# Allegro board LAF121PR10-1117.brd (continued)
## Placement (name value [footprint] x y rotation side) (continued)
J3  -  [JUMP_43X79]  41.12 102.65 270 top
J4  -  [JUMP_43X118]  37.94 55.47 270 top
J5  -  [JUMP_43X79]  39.53 45.69 270 top
JCCG4_T  CVILU_CH31052VA00-NH  [DC021611210]  42.83 115.5 90 bottom
JCRT  ACES_51625-01601-001  [ACES_51625-01601-001_16P-T]  217.65 38.75 90 top
JDIMM1  DEREN_40-42271-26001RHF  [LOTES_ADDR0206-P001A02_260P]  79.15 109.99 90 bottom
JDIMM2  DEREN_40-42261-26001RHF  [LOTES_ADDR0205-P001A02_260P]  66.45 109.99 270 bottom
JEDP1  ACES_51540-04001-P01  [ACES_51540-04001-P01_40P]  212.37 60.45 270 bottom
JFAN1  ACES_50224-00401-001  [ACES_50224-00401-001_4P]  180.51 68.41 45 bottom
JFP  ACES_51522-00601-001  [ACES_51522-00601-001_6P-NPM]  220 30.6 180 bottom
JFP1  ACES_51522-00801-001  [ACES_51522-00801-001_8P]  221 30.6 180 bottom
JH1  ACES_91960-0084N_MX25L3206EM2I  [ACES_91960-0084L_8P-T-NPM]  129.95 40.19 90 bottom
JHDD1  ACES_51625-01201-001  [ACES_51625-01201-001_12P]  190.2 35.7 180 bottom
JHDMI1  CONCR_099AKAC19NBLCNF  [ACON_HMRF6-AK120C_19P-T]  11.05 92.35 90 bottom
JHP1  YUQIU_PJ753-F07J1BE-B  [YUQIU_PJ753-F07J1BE-B_7P-T]  12.65 7.9 90 bottom
JIOB1  ACES_51524-0160N-001  [ACES_51524-0160N-001_16P]  213.2 36.8 180 bottom
JKB1  ACES_50699-03041-P01  [ACES_50699-03041-P01_30P]  82.95 34.05 180 bottom
JKBBL1  ACES_51575-00401-001  [ACES_51575-00401-001_4P-T]  95.05 34.52 180 bottom
JODD1  ACES_50673-0120N-001  [ACES_50673-0120N-001_12P-T]  185.2 64.3 180 bottom
JP2  -  [JUMP_43X39]  158.85 32.2 270 top
JP3  2MM  [JUMP_43X39]  25.89 89.53 180 top
JP4  -  [JUMP_43X79]  190.66 40.42 270 top
JP5  -  [JUMP_43X79]  193.35 65.59 0 top
JP10  -  [JUMP_43X79]  24.04 29.88 270 top
JPWR1  JXT_FP226H-004S1AM  [JXT_FP226H-004S1AM_4P]  221.2 63.65 0 bottom
JRJ45  SANTA_130460-N  [SINGA_2RJ3076-078211F_8P-T]  12.95 77.72 90 bottom
JSPK1  ACES_50224-00401-001  [ACES_50224-00401-001_4P]  16.42 5.88 180 bottom
JSSD1  LCN_DAN05-67306-0103  [LCN_DAN05-67306-0103_75P]  39.38 34.03 180 bottom
JTP1  ACES_51524-0080N-001  [ACES_51524-0080N-001_8P]  125.05 30.5 180 bottom
JUSB1  ACON_TARAN-9R1391  [ACON_TARAN-9R1391_9P]  15.88 56.65 90 bottom
JUSB2  ACON_TARAN-9R1391  [ACON_TARAN-9R1391_9P]  15.88 32.75 90 bottom
JUSBC1  JAE_DX07S024JJ2R1300~D  [JAE_DX07S024JJ2R1300_24P]  7.35 123.82 270 top
JWLAN1  LCN_DAN05-67306-0100  [LCN_DAN05-67306-0100_75P]  79.02 120.65 90 bottom
L1  MCM1012B900F06BP_4P  [INPAQ_MCM1012B900F06BP_4P]  215.73 43.88 180 top
LA1  TAI-TECH HCB1005KF-800T20 0402  [R_0402]  23.92 5.14 180 top
LA2  TAI-TECH HCB1005KF-800T20 0402  [R_0402]  23.92 3.87 180 top
LA3  TAI-TECH HCB1005KF-800T20 0402  [R_0402]  26.83 8.07 270 top
LA4  TAI-TECH HCB1005KF-800T20 0402  [R_0402]  27.88 8.05 270 top
LA6  BLM15PX330SN1D_2P  [MURAT_BLM15PX330SN1D_2P]  18.24 13.58 180 top
LA7  0_0402_5%  [R0402_0OHM]  15.52 20.06 0 bottom
LA8  0_0402_5%  [R0402_0OHM]  18.21 20.06 180 bottom
LA9  BLM15PX330SN1D_2P  [MURAT_BLM15PX330SN1D_2P]  15.61 13.58 0 top
LA10  BLM15BB221SN1D_2P  [MURAT_BLM15BB221SN1D_2P]  35.13 11.49 180 top
LE1  FBMA-L11-160808-800LMT_0603  [KC_FBMA-L11-160808-800LMT_2P]  37.19 87.5 0 top
LE2  FBMA-L11-160808-800LMT_0603  [KC_FBMA-L11-160808-800LMT_2P]  53.67 85.54 270 top
LED1  LTW-295DSKS-5A_YEL-WHITE~D  [LED_LTW-295DSKS-5A_4P]  3.25 133.05 270 bottom
LI1  HCM1012GH900BP_4P  [INPAQ_HCM1012GH900BP_4P]  16.17 94.1 0 top
LI2  HCM1012GH900BP_4P  [INPAQ_HCM1012GH900BP_4P]  16.17 95.94 0 top
LI3  HCM1012GH900BP_4P  [INPAQ_HCM1012GH900BP_4P]  16.17 92.38 0 top
LI4  HCM1012GH900BP_4P  [INPAQ_HCM1012GH900BP_4P]  16.17 90.29 0 top
LT1  MCM1012B900F06BP_4P  [INPAQ_MCM1012B900F06BP_4P]  22.27 131 0 bottom
LT3  MCM1012B900F06BP_4P  [INPAQ_MCM1012B900F06BP_4P]  22.27 129.29 0 bottom
LU1  INPAQ HCM1012GD670A05P  [INPAQ_HCM1012GH900BP_4P]  21.44 58.09 0 top
LU2  INPAQ HCM1012GD670A05P_4P  [INPAQ_HCM1012GH900BP_4P]  21.44 59.81 0 top
LU3  MCM1012B900F06BP_4P  [INPAQ_MCM1012B900F06BP_4P]  31.29 57.78 0 top
LU4  INPAQ HCM1012GD670A05P  [INPAQ_HCM1012GH900BP_4P]  20.29 36.33 90 top
LU5  INPAQ HCM1012GD670A05P  [INPAQ_HCM1012GH900BP_4P]  18.58 36.33 90 top
LU6  MCM1012B900F06BP_4P  [INPAQ_MCM1012B900F06BP_4P]  31.48 39.24 0 bottom
LU7  MCM1012B900F06BP_4P  [INPAQ_MCM1012B900F06BP_4P]  210.53 35.04 270 top
LU8  MCM1012B900F06BP_4P  [INPAQ_MCM1012B900F06BP_4P]  207.87 35.02 270 top
LU13  INPAQ HCM1012GD670A05P  [INPAQ_HCM1012GH900BP_4P]  11.16 123.63 0 top
LU14  INPAQ HCM1012GD670A05P  [INPAQ_HCM1012GH900BP_4P]  12.43 117.91 0 top
LU15  INPAQ HCM1012GD670A05P  [INPAQ_HCM1012GH900BP_4P]  14.31 125.54 180 top
LU16  INPAQ HCM1012GD670A05P  [INPAQ_HCM1012GH900BP_4P]  12.72 119.38 180 top
LV2  BLM15BD121SN1D_0402  [R_0402]  110.11 134.45 270 top
LV3  BLM15BD121SN1D_0402  [R_0402]  109.78 136 59.6 top
LV4  BLM15BD121SN1D_0402  [R_0402]  108.77 134.18 90 bottom
LV6  BLM15BD221SN1D_2P  [MURAT_BLM15BB221SN1D_2P]  126.46 123.65 90 top
LV7  BLM15BD121SN1D_0402  [R_0402]  131.22 119.15 0 top
LV8  BLM15BD121SN1D_0402  [R_0402]  133.82 119.54 180 top
LX1  HCB2012KF-221T30_2P  [TAI-T_HCB2012KF-221T30_2P]  220.97 46.86 0 top
NOREF  -  []  113.08 39.78 0 top
NOREF#2  -  []  6.85 130.5 0 top
NOREF#3  -  []  92.84 -15.43 0 top
NOREF#4  -  []  6.9 112.6 0 top
NOREF#5  -  []  207.45 63.85 0 top
NOREF#6  -  []  126.01 153.05 0 top
NOREF#7  -  []  142.95 117.18 0 top
NOREF#8  -  []  7.4 86.8 0 top
NOREF#9  -  []  8 41.2 0 top
NOREF#10  -  []  137.38 100.81 0 top
NOREF#11  -  []  96.86 53.7 0 top
NOREF#12  -  []  83.03 102.15 0 top
NOREF#13  -  []  77.11 24.94 0 top
NOREF#14  -  []  84.39 53.64 0 top
NOREF#15  -  []  207.45 63.85 0 top
NOREF#16  -  []  -1.24 192.21 0 top
NOREF#17  -  []  169.05 109.5 0 top
NOREF#18  -  []  79.85 93.01 0 top
NOREF#19  -  []  45.5 129.9 0 top
NOREF#20  -  []  93.3 99.96 90 top
NOREF#21  -  []  213.85 65.5 0 top
NOREF#22  -  []  113.08 100.78 0 top
NOREF#23  -  []  137.38 39.78 0 top
NOREF#24  -  []  113.83 93.98 270 top
NOREF#25  -  []  6.67 130.98 0 top
NOREF#26  -  []  99 154 0 top
NOREF#27  -  []  169.05 109.5 0 top
NOREF#28  -  []  101.31 130.35 0 top
NOREF#29  -  []  141.55 27.1 0 top
NOREF#30  -  []  7.9 85.8 0 top
NOREF#31  -  []  134.03 102.94 180 bottom
NOREF#32  -  []  133.97 94.71 180 bottom
NOREF#33  -  []  95.92 50.35 180 bottom
PBATT1  -  [ACES_50458-01001-P01_10P-T]  173.01 40 180 bottom
PC1  1000P_0402_50V7K  [C_0402]  88.18 140.58 270 top
PC2  2200P_0402_25V7K  [C_0402]  87.24 140.58 270 top
PC3  1000P_0402_50V7K  [C_0402]  82.71 148.13 90 top
PC4  2200P_0402_25V7K  [C_0402]  84.62 148.13 90 top
PC5  0.022U_0603_50V7K  [C_0603]  92.01 145.13 270 top
PC6  0.022U_0603_50V7K  [C_0603]  101.47 147.86 180 top
PC7  0.1U_0402_50V7K  [C_0402]  91.99 152.78 0 bottom
PC8  1000P_0603_50V7K  [C_0603]  85.67 147.76 90 top
PC9  2.2U_0402_10V6M  [C_0402]  82.37 141.21 180 top
PC10  0.1U_0402_50V7K  [C_0402]  95.65 144.78 0 bottom
PC11  0.01U_0402_25V7K  [C_0402]  146.62 33.97 270 bottom
PC12  1000P_0402_50V7K  [C_0402]  150.53 39.92 90 bottom
PC13  0.1U_0402_25V6  [C_0402]  169.25 28.94 90 top
PC14  0.1U_0402_25V6  [C_0402]  177.1 28.35 90 top
PC15  10P_0402_50V8J  [C_0402]  89.26 140.63 270 top
PC16  82P_0402_50V8J  [C_0402]  83.66 148.13 90 top
PC17  82P_0402_50V8J  [C_0402]  151.48 39.92 90 bottom
PC18  0.1U_0402_25V7K  [C_0402]  149.58 39.92 90 bottom
PC21  0.1U_0402_10V7K  [C_0402]  92.72 147.52 180 top
PC22  0.1U_0402_10V7K  [C_0402]  86.97 148.26 90 top
PC23  0.1U_0402_10V7K  [C_0402]  88.1 142.65 90 bottom
PC301  1000P_0402_50V7K  [C_0402]  14.09 39.54 180 bottom
PC302  2200P_0402_50V7K  [C_0402]  14.08 42.32 180 bottom
PC303  4.7U_0805_25V6-K  [C_0805]  17.53 41.83 90 top
PC304  4.7U_0805_25V6-K  [C_0805]  16.44 40.97 90 bottom
PC305  0.1U_0402_25V6  [C_0402]  14.12 41.38 180 bottom
PC306  1000P_0402_50V7K  [C_0402]  14.1 40.48 180 bottom
PC307  0.1U_0402_10V7K  [C_0402]  23.48 40.29 90 bottom
PC308  4.7U_0402_6.3V6M  [C_0402]  21.31 43.95 270 top
PC309  680P_0603_50V7K  [C_0603]  22.65 44.38 270 top
PC310  22U_0805_6.3V6M  [C_0805]  24.61 52.77 180 bottom
PC311  22U_0805_6.3V6M  [C_0805]  27.5 52.84 0 bottom
PC312  22U_0805_6.3V6M  [C_0805]  24.53 52.74 180 top
PC313  22U_0805_6.3V6M  [C_0805]  27.5 52.84 0 top
PC314  22U_0805_6.3V6M  [C_0805]  24.63 54.53 180 bottom
PC315  1000P_0402_50V7K  [C_0402]  21.51 46.11 90 bottom
PC316  82P_0402_50V8J  [C_0402]  15.1 40.78 90 bottom
PC501  1000P_0402_50V7K  [C_0402]  25.7 101.85 180 bottom
PC502  2200P_0402_50V7K  [C_0402]  25.7 102.74 180 bottom
PC503  10U_0805_25V6K~D  [C_0805]  28.97 99.08 270 top
PC504  10U_0805_25V6K~D  [C_0805]  28.96 99.08 270 bottom
PC505  0.1U_0402_25V6  [C_0402]  25.7 100.96 180 bottom
PC506  1000P_0402_50V7K  [C_0402]  25.7 100.07 180 bottom
PC507  0.1U_0402_10V7K  [C_0402]  21.87 100.02 270 top
PC508  4.7U_0402_6.3V6M  [C_0402]  23.78 96.69 90 top
PC509  680P_0603_50V7K  [C_0603]  18.77 101.1 90 top
PC510  22U_0805_6.3V6M  [C_0805]  24.1 106.7 270 top
PC511  22U_0805_6.3V6M  [C_0805]  25.82 106.7 270 top
PC512  22U_0805_6.3V6M  [C_0805]  27.53 106.7 270 bottom
PC513  22U_0805_6.3V6M  [C_0805]  25.82 106.7 270 bottom
PC514  22U_0805_6.3V6M  [C_0805]  24.1 106.7 270 bottom
PC515  4.7U_0402_6.3V6M  [C_0402]  24.89 95.55 0 top
PC516  4.7U_0402_6.3V6M  [C_0402]  27.49 92.05 180 bottom
PC517  1000P_0402_50V7K  [C_0402]  25.69 93.04 270 bottom
PC518  82P_0402_50V8J  [C_0402]  25.7 103.63 180 bottom
PC519  22U_0805_6.3V6M  [C_0805]  22.39 106.7 270 top
PC1801  22U_0603_6.3V6M  [C_0603]  180.11 57.52 270 bottom
PC1802  22U_0603_6.3V6M  [C_0603]  174.86 47.03 315 top
PC1803  22U_0603_6.3V6M  [C_0603]  174.86 47.06 315 bottom
PC1804  22U_0603_6.3V6M  [C_0603]  173.41 48.51 135 bottom
PC1805  0.1U_0402_10V7K  [C_0402]  174.62 56.9 90 bottom
PC1806  680P_0402_50V7K  [C_0402]  180.1 53.53 90 top
PC1807  22P_0402_50V8J  [C_0402]  173.77 59.67 0 bottom
PC1808  82P_0402_50V8J  [C_0402]  177.11 60.99 180 bottom
PC1809  0.1U_0402_25V6  [C_0402]  181.22 57.57 270 bottom
PC1810  2200P_0402_50V7K  [C_0402]  177.08 61.88 180 bottom
PC2501  10U_0805_10V6K  [C_0805]  73.63 113.19 90 top
PC2502  10U_0805_10V6K  [C_0805]  64.3 113.5 90 top
PC2503  0.1U_0402_10V7K  [C_0402]  73.19 111.01 270 top
PC2504  1U_0402_10V6K  [C_0402]  72.3 115.43 90 top
PC2505  0.01U_0402_25V7K  [C_0402]  64.74 112.42 270 top
PCA01  2200P_0402_50V7K  [C_0402]  168.37 98.66 90 bottom
PCA02  1000P_0402_50V7K  [C_0402]  167.48 98.66 90 bottom
PCA03  10U_0805_25V6K~D  [C_0805]  164.35 98.14 90 top
PCA04  10U_0805_25V6K~D  [C_0805]  164.34 98.14 90 bottom
PCA05  1000P_0402_50V7K  [C_0402]  166.57 98.65 90 bottom
PCA06  1000P_0402_50V7K  [C_0402]  165.65 98.65 90 bottom
PCA07  0.22U_0402_16V7K  [C_0402]  160.51 86.29 180 bottom
PCA08  680P_0603_50V7K  [C_0603]  155.94 101.72 0 top
PCA101  22U_0603_6.3V6M  [C_0603]  145.88 102.74 180 top
PCA102  22U_0603_6.3V6M  [C_0603]  145.88 101.52 180 top
PCA103  22U_0603_6.3V6M  [C_0603]  145.88 100.3 180 top
PCA104  22U_0603_6.3V6M  [C_0603]  147.04 100.13 270 top
PCA105  22U_0603_6.3V6M  [C_0603]  148.27 100.12 270 top
PCA106  22U_0603_6.3V6M  [C_0603]  150.31 101.23 0 top
PCA107  22U_0603_6.3V6M  [C_0603]  150.31 102.45 0 top
PCA108  22U_0603_6.3V6M  [C_0603]  150.3 103.66 0 top
PCA109  22U_0603_6.3V6M  [C_0603]  150.31 104.88 0 top
PCA110  22U_0603_6.3V6M  [C_0603]  150.31 106.1 0 top
PCA171  470U_X_2VY_R9M  [C_D2]  144.45 103.98 0 bottom
PCA172  470U_X_2VY_R9M  [C_D2]  145.61 99.48 270 bottom
PCB01  0.1U_0402_25V6  [C_0402]  200.25 52.84 270 bottom
PCB02  2200P_0402_50V7K  [C_0402]  199.36 52.84 270 bottom
PCB03  22U_0805_25V6M  [C_0805]  200.6 55.86 0 top
PCB04  22U_0805_25V6M  [C_0805]  200.6 54.14 0 top
PCB05  22U_0805_25V6M  [C_0805]  200.6 55.86 0 bottom
PCB06  22U_0805_25V6M  [C_0805]  200.6 54.14 0 bottom
PCB07  33U_D2_25VM_R40M  [C_EEFCX1E330R-NPM]  192.24 58.17 180 bottom
PCB08  33U_25V_M  [C_6P3X4P5]  192.65 58.26 0 bottom
PCB10  10U_0805_25V6K~D  [C_0805]  181.64 45.97 90 bottom
PCB11  10U_0805_25V6K~D  [C_0805]  181.71 41.49 270 bottom
PCB12  10U_0805_25V6K~D  [C_0805]  181.64 45.97 90 top
PCB13  10U_0805_25V6K~D  [C_0805]  189.54 39.91 270 bottom
PCB14  10U_0805_25V6K~D  [C_0805]  183.42 41.49 270 bottom
PCB15  10U_0805_25V6K~D  [C_0805]  183.42 45.94 90 top
PCB16  10U_0805_25V6K~D  [C_0805]  181.71 41.49 270 top
PCB17  10U_0805_25V6K~D  [C_0805]  183.42 41.49 270 top
PCB18  4.7U_0402_6.3V6M  [C_0402]  201.04 48.07 270 bottom
PCB19  1U_0402_25V6K  [C_0402]  201.13 48.79 180 top
PCB20  1U_0402_25V6K  [C_0402]  201.13 47.85 180 top
PCB21  0.1U_0402_25V6  [C_0402]  180.32 45.21 180 bottom
PCB22  2200P_0402_50V7K  [C_0402]  180.32 46.1 180 bottom
PCB23  2200P_0402_50V7K  [C_0402]  185.52 39.88 225 bottom
PCB24  1000P_0402_50V7K  [C_0402]  180.32 46.99 180 bottom
PCB25  0.22U_0603_25V7K  [C_0603]  199.57 44.9 270 bottom
PCB26  0.1U_0402_25V6  [C_0402]  201.09 50.97 180 bottom
PCB27  1U_0603_50V6K  [C_0603]  203.49 50.71 90 top
PCB28  1U_0402_10V6K  [C_0402]  207.6 51.37 0 bottom
PCB29  1U_0402_10V6K  [C_0402]  203.48 43.73 0 top
PCB30  0.22U_0603_25V7K  [C_0603]  203.07 41.87 270 bottom
PCB31  10U_0805_25V6K~D  [C_0805]  178.09 44.99 90 top
PCB32  10U_0805_25V6K~D  [C_0805]  178.09 44.99 90 bottom
PCB33  4700P_0402_25V7K  [C_0402]  146.64 30.89 90 bottom
PCB34  10P_0402_50V8J  [C_0402]  206.74 45.44 180 top
PCB35  0.1U_0402_25V6  [C_0402]  204.31 41.92 270 top
PCB36  680P_0603_50V7K  [C_0603]  187.28 51.51 270 top
PCB37  680P_0603_50V7K  [C_0603]  188.48 44.42 90 top
PCB38  1U_0402_25V6K  [C_0402]  205.22 41.92 270 top
PCB39  560P_0402_50V7K  [C_0402]  208.23 46.16 0 bottom
PCB40  0.1U_0402_25V6  [C_0402]  210.02 43.48 0 bottom
PCB41  1U_0402_25V6K  [C_0402]  206.13 41.2 180 bottom
PCB42  0.01U_0402_25V7K  [C_0402]  210.04 47.03 270 bottom
PCB43  0.22U_0402_25V6K  [C_0402]  206.14 41.91 270 top
PCB44  0.1U_0402_10V7K  [C_0402]  168.04 34.34 90 top
PCB45  0.1U_0402_25V6  [C_0402]  208.24 42.65 0 top
PCB46  82P_0402_50V8J  [C_0402]  180.32 44.32 180 bottom
PCB47  82P_0402_50V8J  [C_0402]  191.28 61.05 180 bottom
PCF01  22U_0603_6.3V6M  [C_0603]  78.47 113.27 90 top
PCF02  22U_0603_6.3V6M  [C_0603]  87.36 110.07 180 top
PCF03  0.1U_0402_10V7K  [C_0402]  77.84 115.77 90 top
PCF04  1U_0402_10V6K  [C_0402]  81.22 110.61 0 top
PCF05  0.01U_0402_25V7K  [C_0402]  87.23 114.24 90 top
PCF06  22U_0603_6.3V6M  [C_0603]  87.39 111.32 180 top
PCH01  0.1U_0402_25V6  [C_0402]  164.8 50.26 90 top
PCH02  2200P_0402_50V7K  [C_0402]  164.82 50.27 90 bottom
PCH03  10U_0805_25V6K~D  [C_0805]  164.67 49.01 180 bottom
PCH04  10U_0805_25V6K~D  [C_0805]  166.2 49.32 90 bottom
PCH05  22U_0603_6.3V6M  [C_0603]  156.63 43.94 0 top
PCH06  22U_0603_6.3V6M  [C_0603]  156.63 47.62 0 top
PCH07  22U_0603_6.3V6M  [C_0603]  156.63 46.41 0 top
PCH08  22U_0603_6.3V6M  [C_0603]  156.63 45.14 0 top
PCH09  0.1U_0402_25V6  [C_0402]  167.11 47.69 0 top
PCH10  1U_0402_10V6K  [C_0402]  167.17 45.99 0 bottom
PCH11  1U_0402_10V6K  [C_0402]  167.17 44.31 0 top
PCH12  0.1U_0402_10V7K  [C_0402]  162.86 42.57 180 bottom
PCH13  680P_0603_50V7K  [C_0603]  160.38 43.03 0 top
PCH14  330P_0402_50V7K  [C_0402]  169.82 45.96 180 top
PCH15  1000P_0402_50V7K  [C_0402]  163.91 50.27 90 bottom
PCH16  1000P_0402_50V7K  [C_0402]  163.91 50.29 90 top
PCH17  82P_0402_50V8J  [C_0402]  163.05 50.29 180 top
PCH18  100P_0402_50V8J  [C_0402]  165.03 45.28 180 top
PCH19  100P_0402_50V8J  [C_0402]  162.44 44.12 90 top
PCH20  0.1U_0402_25V6  [C_0402]  166.65 50.62 90 top
PCM01  0.1U_0402_25V6  [C_0402]  42.76 28.02 90 top
PCM02  2200P_0402_50V7K  [C_0402]  41.84 28.02 90 top
PCM03  4.7U_0805_25V6-K  [C_0805]  42.48 25.9 270 bottom
PCM04  4.7U_0805_25V6-K  [C_0805]  41.82 25.9 270 top
PCM05  22U_0603_6.3V6M  [C_0603]  49.81 31.84 90 top
PCM06  22U_0603_6.3V6M  [C_0603]  49.79 31.85 90 bottom
PCM07  22U_0603_6.3V6M  [C_0603]  51.01 31.85 90 bottom
PCM08  22U_0603_6.3V6M  [C_0603]  48.6 31.85 90 bottom
PCM09  22U_0603_6.3V6M  [C_0603]  48.6 31.84 90 top
PCM10  22U_0603_6.3V6M  [C_0603]  51.01 31.84 90 top
PCM11  680P_0402_50V7K  [C_0402]  51.98 27.96 180 top
PCM12  0.1U_0402_10V7K  [C_0402]  40.81 27.49 180 top
PCM13  1U_0603_10V6K  [C_0603]  36.76 25.3 270 top
PCM14  1U_0603_10V6K  [C_0603]  32.95 25.3 270 top
PCM15  0.1U_0402_10V7K  [C_0402]  33.63 29.13 180 top
PCM16  0.1U_0402_10V7K  [C_0402]  32.72 30.06 180 top
PCM17  220P_0402_50V8J  [C_0402]  34.04 32.25 0 top
PCM18  0.1U_0402_25V6  [C_0402]  35.86 32.21 90 top
PCM19  0.033U_0402_16V7K  [C_0402]  36.78 32.19 90 top
PCM20  10U_0603_6.3V6M  [C_0603]  38.11 33.75 90 top
PCM21  10U_0603_6.3V6M  [C_0603]  38.32 32.29 0 top
PCM22  1000P_0402_50V7K  [C_0402]  41.84 28.02 90 bottom
PCM23  1000P_0402_50V7K  [C_0402]  42.76 28.02 90 bottom
PCM24  82P_0402_50V8J  [C_0402]  47.47 26.39 270 top
PCS01  0.01U_0402_25V7K  [C_0402]  53.77 117.09 180 top
PCS02  100P_0402_50V8J  [C_0402]  47.47 115.13 270 top
PCS03  220P_0402_50V8J  [C_0402]  50.26 117.33 90 top
PCS04  1200P_0402_50V7K  [C_0402]  48.23 117.9 90 top
PCS05  100P_0402_50V8J  [C_0402]  37.26 127.69 0 bottom
PCS06  1000P_0402_50V7K  [C_0402]  37.27 128.61 0 bottom
PCS07  0.1U_0402_25V6  [C_0402]  40.34 128.7 270 bottom
PCS08  100P_0402_50V8J  [C_0402]  39.44 128.7 270 bottom
PCS09  0.47U_0603_25V7K  [C_0603]  52 136.06 0 top
PCS10  1500P_0402_50V7K  [C_0402]  65.34 138.55 90 top
PCS11  0.1U_0402_10V7K  [C_0402]  58.82 131.76 0 top
PCS12  0.1U_0402_10V7K  [C_0402]  56.42 128.38 90 top
PCS13  0.1U_0402_10V7K  [C_0402]  57.44 124.66 270 top
PCS14  0.1U_0402_10V7K  [C_0402]  56.49 124.66 270 top
PCS15  1000P_0603_50V7K  [C_0603]  77.12 142.64 0 top
PCS16  2.2U_0402_10V6M  [C_0402]  79.73 142.58 0 top
PCS17  0.1U_0402_10V7K  [C_0402]  62.26 126.22 90 top
PCS19  0.1U_0402_25V6  [C_0402]  63.16 124.27 0 top
PCS20  0.1U_0402_25V6  [C_0402]  63.33 117.85 0 top
PCS61  1500P_0402_50V7K  [C_0402]  48.09 134.95 90 top
PCS62  0.1U_0402_10V7K  [C_0402]  40.69 127.77 0 top
PCS63  4.7U_0603_25V6K  [C_0603]  59.46 137.45 225 top
PCV01  10U_0805_25V6K~D  [C_0805]  81.78 134.78 270 bottom
PCV02  10U_0805_25V6K~D  [C_0805]  81.78 134.78 270 top
PCV03  4.7U_0805_25V6-K  [C_0805]  83.56 134.78 270 top
PCV04  2200P_0402_50V7K  [C_0402]  82.23 139.11 180 bottom
PCV05  0.1U_0402_25V6K  [C_0402]  82.23 138.22 180 bottom
PCV06  2200P_0402_50V7K  [C_0402]  80.46 134.95 270 top
PCV07  0.1U_0402_25V6K  [C_0402]  82.23 136.44 180 bottom
PCV08  0.22U_0402_16V7K  [C_0402]  78.39 132.28 270 top
PCV09  680P_0603_50V7K  [C_0603]  92.42 131.71 0 top
PCV10  0.1U_0402_25V6K  [C_0402]  69.63 130.16 90 top
PCV11  1U_0603_10V6K  [C_0603]  80.74 129.73 0 top
PCV12  1U_0603_10V6K  [C_0603]  80.74 131 0 top
PCV13  10U_0805_25V6K~D  [C_0805]  81.69 124.79 90 bottom
PCV14  10U_0805_25V6K~D  [C_0805]  81.69 124.79 90 top
PCV15  4.7U_0805_25V6-K  [C_0805]  83.49 124.81 90 bottom
PCV16  2200P_0402_50V7K  [C_0402]  81.82 122.46 180 top
PCV17  0.1U_0402_25V6  [C_0402]  81.82 123.35 180 top
PCV18  2200P_0402_50V7K  [C_0402]  81.82 122.46 180 bottom
PCV19  0.1U_0402_25V6  [C_0402]  81.82 123.35 180 bottom
PCV20  1000P_0402_50V7K  [C_0402]  68.87 128.53 270 top
PCV21  0.22U_0402_16V7K  [C_0402]  79.68 128.33 180 top
PCV22  0.22U_0402_16V7K  [C_0402]  68.87 126.63 270 top
PCV23  0.22U_0402_16V7K  [C_0402]  70.66 125.79 180 top
PCV24  680P_0603_50V7K  [C_0603]  92.45 128.16 0 top
PCV25  1000P_0402_50V7K  [C_0402]  74.66 125.34 180 top
PCV26  180P_0402_50V8J  [C_0402]  73.68 122.8 0 top
PCV27  330P_0402_50V7K  [C_0402]  75.4 124.39 0 top
PCV28  0.033U_0402_16V7K  [C_0402]  70.96 123.49 90 top
PCV29  390P_0402_50V7K  [C_0402]  75.41 121.08 90 top
PCV30  0.15U_0603_16V7K  [C_0603]  69.21 122.99 180 top
PCV31  330P_0402_50V7K  [C_0402]  72.82 121.03 180 top
PCV32  0.1U_0603_50V7K  [C_0603]  69.21 124.19 180 top
PCV33  820P_0402_50V7K  [C_0402]  71.78 125.34 0 top
PCV34  0.01U_0402_25V7K  [C_0402]  76.44 125.34 180 top
PCV35  4.7U_0805_25V6-K  [C_0805]  83.56 134.78 270 bottom
PCV36  4.7U_0805_25V6-K  [C_0805]  83.48 124.82 90 top
PCV37  0.22U_0402_16V7K  [C_0402]  67.06 129.23 270 top
PCV171  560U_D2_2VM_R4.5M  [C_D2]  102.9 136.8 90 bottom
PCV172  560U_D2_2VM_R4.5M  [C_D2]  103.38 123.89 270 bottom
PCW01  0.1U_0402_25V6  [C_0402]  138.46 108.22 270 bottom
PCW02  2200P_0402_50V7K  [C_0402]  135.66 108.78 270 bottom
PCW03  10U_0805_25V6K~D  [C_0805]  139.78 109.41 270 top
PCW04  10U_0805_25V6K~D  [C_0805]  139.8 109.37 270 bottom
PCW05  22U_0603_6.3V6M  [C_0603]  154.22 111.67 90 top
PCW06  22U_0603_6.3V6M  [C_0603]  154.31 109.23 270 top
PCW07  22U_0603_6.3V6M  [C_0603]  154.23 111.65 90 bottom
PCW08  22U_0603_6.3V6M  [C_0603]  154.31 109.23 270 bottom
PCW09  0.1U_0402_25V6  [C_0402]  138.22 111.51 90 bottom
PCW10  1U_0402_10V6K  [C_0402]  142.54 111.51 180 bottom
PCW11  1U_0402_10V6K  [C_0402]  144.29 111.43 90 bottom
PCW12  0.1U_0402_10V7K  [C_0402]  147.13 108.23 0 top
PCW13  680P_0603_50V7K  [C_0603]  149.8 111.27 90 top
PCW14  330P_0402_50V7K  [C_0402]  147.16 113.52 90 bottom
PCW15  1000P_0402_50V7K  [C_0402]  137.57 108.23 270 bottom
PCW16  1000P_0402_50V7K  [C_0402]  134.71 108.83 270 bottom
PCW17  82P_0402_50V8J  [C_0402]  136.66 108.22 270 bottom
PCZ01  330P_0402_50V7K  [C_0402]  162.94 87.82 180 bottom
PCZ02  390P_0402_50V7K  [C_0402]  160.17 87.99 180 bottom
PCZ03  1000P_0402_50V7K  [C_0402]  161.97 91.21 180 bottom
PCZ04  220P_0402_50V8J  [C_0402]  159.44 88.22 270 top
PCZ05  330P_0402_50V7K  [C_0402]  162.87 89.5 90 bottom
PCZ06  0.022U_0402_25V7K  [C_0402]  160.57 91.37 270 top
PCZ07  0.1U_0603_50V7K  [C_0603]  159.61 91.97 180 top
PCZ08  0.1U_0603_50V7K  [C_0603]  160.71 89.38 0 top
PCZ09  220P_0402_50V8J  [C_0402]  159.77 89.15 180 top
PCZ10  33U_25V_M  [C_25CL33LD]  167.37 75.51 180 bottom
PCZ11  1000P_0402_50V7K  [C_0402]  155.75 89.73 90 bottom
PCZ12  33U_25V_M  [C_25CL33LD]  167.5 82.89 90 bottom
PCZ13  10U_0805_25V6K~D  [C_0805]  164.59 70.58 180 bottom
PCZ14  10U_0805_25V6K~D  [C_0805]  168.03 65.71 270 top
PCZ15  10U_0805_25V6K~D  [C_0805]  168.03 65.71 270 bottom
PCZ16  2200P_0402_50V7K  [C_0402]  167.41 70.16 0 bottom
PCZ17  0.1U_0402_25V6K  [C_0402]  167.41 71.05 0 bottom
PCZ18  0.1U_0402_25V6K  [C_0402]  167.41 69.27 0 bottom
PCZ19  10U_0805_25V6K~D  [C_0805]  164.59 70.59 180 top
PCZ20  2200P_0402_50V7K  [C_0402]  167.41 68.38 0 bottom
PCZ21  0.1U_0402_25V6K  [C_0402]  154.85 91.08 270 bottom
PCZ22  1U_0603_10V6K  [C_0603]  153.06 80.62 0 top
PCZ23  1U_0603_10V6K  [C_0603]  155.75 80.56 315 top
PCZ24  0.22U_0402_16V7K  [C_0402]  156.24 81.72 90 top
PCZ25  1000P_0402_50V7K  [C_0402]  152.93 89.96 90 bottom
PCZ26  680P_0603_50V7K  [C_0603]  161.02 60.6 90 top
PCZ27  0.22U_0402_16V7K  [C_0402]  150.3 89.57 180 top
PCZ28  0.22U_0402_16V7K  [C_0402]  150.3 88.68 180 top
PCZ29  1000P_0402_50V7K  [C_0402]  147 84.89 90 top
PCZ30  150P_0402_50V8J  [C_0402]  150.35 85.81 270 top
PCZ31  330P_0402_50V7K  [C_0402]  147.86 84.06 270 top
PCZ32  0.033U_0402_16V7K  [C_0402]  148.17 87.77 0 top
PCZ33  390P_0402_50V7K  [C_0402]  148.78 84.06 270 top
PCZ34  0.15U_0603_16V7K  [C_0603]  148.32 88.69 90 top
PCZ35  2200P_0402_50V7K  [C_0402]  155.7 74.33 0 top
PCZ36  33U_D2_25VM_R40M  [C_EEFCX1E330R-NPM]  167.79 75.51 0 bottom
PCZ37  33U_D2_25VM_R40M  [C_EEFCX1E330R-NPM]  167.53 82.69 270 bottom
PCZ38  10U_0805_25V6K~D  [C_0805]  159.04 77.44 270 bottom
PCZ39  2200P_0402_50V7K  [C_0402]  155.61 74.56 0 bottom
PCZ40  0.1U_0402_25V6K  [C_0402]  155.61 73.63 0 bottom
PCZ41  10U_0805_25V6K~D  [C_0805]  157.32 77.44 270 bottom
PCZ42  330P_0402_50V7K  [C_0402]  151 85.72 0 bottom
PCZ43  10U_0805_25V6K~D  [C_0805]  157.32 77.44 270 top
PCZ44  10U_0805_25V6K~D  [C_0805]  159.04 77.44 270 top
PCZ45  0.1U_0402_25V6K  [C_0402]  155.7 73.44 0 top
PCZ46  0.1U_0603_50V7K  [C_0603]  149.26 88.9 90 bottom
PCZ47  820P_0402_50V7K  [C_0402]  146.82 90.62 0 bottom
PCZ48  0.22U_0402_16V7K  [C_0402]  152.74 81.64 90 top
PCZ49  0.01U_0402_25V7K  [C_0402]  151.47 87.82 0 bottom
PCZ50  680P_0603_50V7K  [C_0603]  159.44 60.6 90 top
PCZ101  22U_0603_6.3V6M  [C_0603]  170.4 54.9 0 top
PCZ102  22U_0603_6.3V6M  [C_0603]  170.39 56.14 0 top
PCZ103  22U_0603_6.3V6M  [C_0603]  126.32 67.2 90 top
PCZ104  22U_0603_6.3V6M  [C_0603]  127.54 67.2 90 top
PCZ105  22U_0603_6.3V6M  [C_0603]  128.76 67.2 90 top
PCZ106  22U_0603_6.3V6M  [C_0603]  123.07 65.4 270 top
PCZ107  22U_0603_6.3V6M  [C_0603]  124.29 65.4 270 top
PCZ108  22U_0603_6.3V6M  [C_0603]  125.51 65.4 270 top
PCZ109  22U_0603_6.3V6M  [C_0603]  126.73 65.4 270 top
PCZ110  22U_0603_6.3V6M  [C_0603]  127.95 65.4 270 top
PCZ111  22U_0603_6.3V6M  [C_0603]  131.25 73.48 270 top
PCZ112  22U_0603_6.3V6M  [C_0603]  130.02 74.1 270 top
PCZ113  22U_0603_6.3V6M  [C_0603]  132.56 72.96 270 top
PCZ114  22U_0603_6.3V6M  [C_0603]  130.13 69.13 90 top
PCZ115  22U_0603_6.3V6M  [C_0603]  154.38 54.17 270 top
PCZ116  22U_0603_6.3V6M  [C_0603]  162.25 54.17 270 top
PCZ117  22U_0603_6.3V6M  [C_0603]  163.52 54.17 270 top
PCZ118  22U_0603_6.3V6M  [C_0603]  167.27 54.17 270 top
PCZ119  22U_0603_6.3V6M  [C_0603]  166 54.17 270 top
PCZ120  22U_0603_6.3V6M  [C_0603]  164.73 54.17 270 top
PCZ171  470U_X_2VY_R9M  [C_D2]  154.42 51.7 0 bottom
PCZ172  470U_X_2VY_R9M  [C_D2]  149.94 59.28 270 bottom
PCZ173  470U_X_2VY_R9M  [C_D2]  170.84 53.65 90 bottom
PCZ174  470U_X_2VY_R9M  [C_D2]  148.05 63.48 90 bottom
PD1  -  [TVNST52302AB0_SOT523-3]  54.07 118.3 90 top
PD2  -  [BAV99W_SC70-3]  61.5 120.81 0 top
PD3  -  [BAV99W_SC70-3]  61.5 116.1 180 top
PD4  S SCH DIO 5A 100V 15UA 0.88V TO227-3  [PDS5100H-13_POWERDI5-3]  96.51 140.89 180 top
PD5  -  [TVNST52302AB0_SOT523-3]  166.82 40.38 180 top
PD6  -  [TVNST52302AB0_SOT523-3]  170.02 39.38 180 top
PD10  -  [LRB715FT1G_SOT323-3]  94 150.96 90 top
PD11  -  [LRB715FT1G_SOT323-3]  82.63 138.14 0 top
PD12  -  [DFLS160-7_POWERDI123-2]  84.68 146.19 0 top
PD501  -  [SDMK0340L-7-F_SOD323-2]  28.86 88.01 90 bottom
PDB01  -  [SDMK0340L-7-F_SOD323-2]  204.19 54.61 0 bottom
PDB02  -  [SDMK0340L-7-F_SOD323-2]  204.19 56.32 0 bottom
PDB03  -  [SDMK0340L-7-F_SOD323-2]  203.35 58.88 135 bottom
PDB04  -  [BAT54CW_SOT323-3]  167.6 37.12 270 top
PDB05  -  [SDMK0340L-7-F_SOD323-2]  169.4 36.66 270 top
PDS01  -  [BAT54CW_SOT323-3]  54.71 120.01 180 top
PDS02  S SCH DIO 5A 100V 15UA 0.88V TO227-3  [PDS5100H-13_POWERDI5-3]  65.1 134.23 180 top
PDS03  -  [LRB715FT1G_SOT323-3]  53.43 119.3 90 top
PDS04  -  [SDMK0340L-7-F_SOD323-2]  45.25 121.59 270 top
PDS05  -  [SDMK0340L-7-F_SOD323-2]  47.54 121.79 0 top
PDS06  -  [SDMK0340L-7-F_SOD323-2]  47.54 120.07 0 top
PH1  100K_0402_1%_TSM0B104F4251RZ  [R_0402]  120.75 47.67 90 top
PHA01  10K_0402_5%_ERTJ0ER103J  [R_0402]  156.4 93.45 180 bottom
PHA02  470K_0402_5%_TSM0B474J4702RE  [R_0402]  159.94 94.55 180 bottom
PHV01  470K_0402_5%_TSM0B474J4702RE  [R_0402]  90.25 121.6 0 bottom
PHV02  10K_0402_5%_ERTJ0ER103J  [R_0402]  94.2 119.85 135 bottom
PHZ01  470K_0402_5%_TSM0B474J4702RE  [R_0402]  160.14 71.36 90 bottom
PHZ02  10K_0402_5%_ERTJ0ER103J  [R_0402]  152.31 62.77 270 bottom
PJP1  JUMP_43X79  [JUMP_43X79-NPM]  88.44 144.05 90 top
PJP2  JUMP_43X79  [JUMP_43X79-NPM]  74.29 145.17 90 top
PJP3  JUMP_43X79  [JUMP_43X79-NPM]  148.98 35.84 90 bottom
PJP301  JUMP_43X39  [JUMP_43X39-NPM]  18.7 37.62 90 bottom
PJP302  -  [JUMP_43X118]  28.49 56.35 0 bottom
PJP501  JUMP_43X79  [JUMP_43X79-NPM]  28.04 102.84 270 bottom
PJP502  -  [JUMP_43X79]  24.42 108.54 90 bottom
PJP503  -  [JUMP_43X79]  28.28 108.57 90 bottom
PJP1801  -  [JUMP_43X39]  180.78 59.61 180 top
PJP1802  -  [JUMP_43X79]  173.03 46.41 225 bottom
PJP2501  -  [JUMP_43X39]  75.89 114.75 270 top
PJP2502  -  [JUMP_43X39]  60.59 112.2 180 top
PJPA01  -  [JUMP_43X79]  166.06 95.62 180 bottom
PJPB01  PAD-OPEN 4X4M  [JUMP_43X118-NPM]  187.32 58.51 0 bottom
PJPDC1  ACES_50458-00601-001  [ACES_50458-00601-001_6P-T]  75.27 143.96 0 bottom
PJPF01  -  [JUMP_43X39]  79.54 110.29 90 top
PJPF02  -  [JUMP_43X39]  89.74 112.74 0 top
PJPH01  JUMP_43X39  [JUMP_43X39-NPM]  168.18 50.55 270 bottom
PJPH02  -  [JUMP_43X118]  155.84 35.94 180 top
PJPM01  JUMP_43X39  [JUMP_43X39-NPM]  49.02 25.12 90 top
PJPM02  -  [JUMP_43X118]  44.8 31.69 90 bottom
PJPM03  -  [JUMP_43X39]  40.12 33.92 90 top
PJPS01  PAD-OPEN 4X4M  [JUMP_43X118]  45.24 137.88 180 bottom
PJPV01  JUMP_43X79  [JUMP_43X79-NPM]  88.65 140.25 180 bottom
PJPW01  JUMP_43X39  [JUMP_43X39-NPM]  135.2 111.2 270 bottom
PJPW02  -  [JUMP_43X118]  157.52 111.65 90 bottom
PJPZ01  JUMP_43X79  [JUMP_43X79-NPM]  171.67 78.91 135 bottom
PL1  5A Z150 20M 1210_2P  [5A_Z150_1210_2P]  88.44 143.25 90 top
PL2  5A Z150 20M 1210_2P  [5A_Z150_1210_2P]  74.29 144.37 90 top
PL3  BLM15AG102SN1D_2P  [MURAT_BLM15AG102SN1D_2P]  56.49 116.79 90 top
PL4  5A Z150 20M 1210_2P  [5A_Z150_1210_2P]  148.98 35.04 90 bottom
PL301  1.5UH_9A_20%_7X7X3_M  [L_7X7X3_M_2P]  26.1 43.87 90 bottom
PL311  5A_Z120_25M_0805_2P  [TAI-T_HCB2012KF-121T50_2P]  18.7 37.22 90 bottom
PL501  1.5UH_9A_20%_7X7X3_M  [L_7X7X3_M_2P]  19.34 98.82 90 bottom
PL511  5A Z150 20M 1210_2P  [5A_Z150_1210_2P]  28.1 103.66 270 bottom
PL1801  1UH_6.6A_20%_5X5X3_M  [L_5X5X3_M_2P]  177.35 53.83 270 bottom
PL1811  5A_Z120_25M_0805_2P  [TAI-T_HCB2012KF-121T50_2P]  182.2 58.9 180 bottom
PLA01  0.15UH_MMD-06DZER15MEM1L__36A_20%  [L_7X7X4_M]  156 97.73 180 bottom
PLB01  1UH_PCMB104T-1R0MH_18A_20%  [CYNTE_PCMB104T-1R0MH_2P]  187.88 52.98 270 bottom
PLB11  5A Z150 20M 1210_2P  [5A_Z150_1210_2P]  186.52 58.51 0 bottom
PLH01  1UH_11A_20%_7X7X3_M  [L_7X7X3_M_2P]  160.35 45.59 180 bottom
PLH11  5A_Z120_25M_0805_2P  [TAI-T_HCB2012KF-121T50_2P]  168.18 50.95 270 bottom
PLM01  1UH_11A_20%_7X7X3_M  [L_7X7X3_M_2P]  54.73 27.6 180 bottom
PLM11  5A_Z120_25M_0805_2P  [TAI-T_HCB2012KF-121T50_2P]  49.02 24.72 90 top
PLS11  5A_Z120_25M_0805_2P  [TAI-T_HCB2012KF-121T50_2P]  37 130.02 0 bottom
PLS12  5A_Z120_25M_0805_2P  [TAI-T_HCB2012KF-121T50_2P]  37 131.81 0 bottom
PLV01  0.22UH_24A_20%_7X7X4_MOLDING  [L_7X7X4_M]  97.21 122.95 135 bottom
PLV02  0.22UH_24A_20%_7X7X4_MOLDING  [L_7X7X4_M]  97.39 137.94 225 bottom
PLV11  5A Z150 20M 1210_2P  [5A_Z150_1210_2P]  89.44 140.21 180 bottom
PLW01  1UH_6.6A_20%_5X5X3_M  [L_5X5X3_M_2P]  147.39 110.16 0 bottom
PLW11  5A_Z120_25M_0805_2P  [TAI-T_HCB2012KF-121T50_2P]  135.2 111.6 270 bottom
PLZ01  5A Z150 20M 1210_2P  [5A_Z150_1210_2P]  170.31 80.19 315 bottom
PLZ02  0.15UH_MMD-06DZER15MEM1L__36A_20%  [L_7X7X4_M]  164.43 62.12 270 bottom
PLZ03  0.15UH_MMD-06DZER15MEM1L__36A_20%  [L_7X7X4_M]  156.51 64.41 270 bottom
PQ1  -  [FDV301N-G_SOT23-3]  57.95 118.35 0 top
PQ2  -  [MMST3904-7-F_SOT323-3]  59.53 115.88 90 top
PQ3  -  [AON7409_DFN8-5]  93.55 146.07 270 top
PQ4  -  [AON7409_DFN8-5]  101.13 144.37 90 top
PQ5  2N7002KW_SOT323-3  [DMN65D8LW-7_SOT323-3]  91.71 149.69 0 bottom
PQ6  2N7002KW_SOT323-3  [DMN65D8LW-7_SOT323-3]  93.86 146.16 180 bottom
PQ11  2N7002KW_SOT323-3  [DMN65D8LW-7_SOT323-3]  174.09 30.35 90 top
PQ12  2N7002KDW_SOT363-6  [DMN65D8LDW-7_SOT363-6]  172.13 29.25 90 top
PQ13  2N7002KDW_SOT363-6  [DMN65D8LDW-7_SOT363-6]  173.28 33.99 0 top
PQ15  2N7002KW_SOT323-3  [DMN65D8LW-7_SOT323-3]  93.78 148.52 270 bottom
PQ16  2N7002KW_SOT323-3  [DMN65D8LW-7_SOT323-3]  90.75 148.48 270 top
PQ17  2N7002KW_SOT323-3  [DMN65D8LW-7_SOT323-3]  89.82 147.37 180 bottom
PQ18  2N7002KW_SOT323-3  [DMN65D8LW-7_SOT323-3]  91.1 143.51 90 bottom
PQ19  -  [AO3409_SOT23-3]  101.28 146.77 270 bottom
PQ20  2N7002KW_SOT323-3  [DMN65D8LW-7_SOT323-3]  94.72 142.54 135 bottom
PQA01  AON6992_DFN5X6D-8-7  [AON6970_DFN5X6D-8-7]  162.61 96.11 180 bottom
PQB01  -  [AON6994_DFN5X6D-8-7]  194.27 53.58 0 bottom
PQB02  -  [AON6994_DFN5X6D-8-7]  194.5 37.7 135 bottom
PQB03  -  [AON7409_DFN8-5]  149.98 30.46 180 bottom
PQB04  2N7002KW_SOT323-3  [DMN65D8LW-7_SOT323-3]  163.6 32.49 0 top
PQH01  2N7002KW_SOT323-3  [DMN65D8LW-7_SOT323-3]  165.45 43.53 270 top
PQH02  2N7002KDW_SOT363-6  [DMN65D8LDW-7_SOT363-6]  167.63 50.24 270 top
PQM01  PE642DT_PDFN8-10  [AON7934_DFN3X3A8-10]  44.08 28.09 0 bottom
PQS01  -  [AON7409_DFN8-5]  54.11 139.56 270 top
PQS02  -  [AON7409_DFN8-5]  63.95 137.63 90 top
PQS03  2N7002KDW_SOT363-6  [DMN65D8LDW-7_SOT363-6]  56.47 130.87 0 top
PQS04  2N7002KW_SOT323-3  [DMN65D8LW-7_SOT323-3]  54.52 131.12 0 top
PQS05  2N7002KDW_SOT363-6  [DMN65D8LDW-7_SOT363-6]  58.2 129.68 270 top
PQS06  -  [AO3409_SOT23-3]  62.18 129.54 270 top
PQS07  2N7002KW_SOT323-3  [DMN65D8LW-7_SOT323-3]  65.31 126.11 270 top
PQS08  2N7002KW_SOT323-3  [DMN65D8LW-7_SOT323-3]  49.5 125.21 0 top
PQS10  2N7002KDW_SOT363-6  [DMN65D8LDW-7_SOT363-6]  63.37 121.4 0 top
PQS11  2N7002KW_SOT323-3  [DMN65D8LW-7_SOT323-3]  65.31 119.57 270 top
PQS12  2N7002KW_SOT323-3  [DMN65D8LW-7_SOT323-3]  50.65 129.22 90 top
PQS13  -  [AO3409_SOT23-3]  50.17 133.47 270 top
PQS14  2N7002KW_SOT323-3  [DMN65D8LW-7_SOT323-3]  69 135.44 0 top
PQS30  2N7002KDW_SOT363-6  [DMN65D8LDW-7_SOT363-6]  45.01 123.46 90 top
PQS61  -  [AON7409_DFN8-5]  50.68 137.63 90 top
PQS62  2N7002KW_SOT323-3  [DMN65D8LW-7_SOT323-3]  57.23 135.84 0 top
PQS63  -  [AO3409_SOT23-3]  44.84 137.59 180 top
PQS64  2N7002KW_SOT323-3  [DMN65D8LW-7_SOT323-3]  40.65 130.83 0 top
PQV01  -  [AON6994_DFN5X6D-8-7]  85.17 122.38 0 top
PQV02  -  [AON6994_DFN5X6D-8-7]  88.98 122.38 180 bottom
PQV03  -  [AON6994_DFN5X6D-8-7]  89.03 137.5 180 top
PQV04  -  [AON6994_DFN5X6D-8-7]  85.22 137.5 0 bottom
PQZ01  AON6994_DFN5X6D-8-7  [AON6970_DFN5X6D-8-7]  166.49 68.89 270 bottom
PQZ02  AON6994_DFN5X6D-8-7  [AON6970_DFN5X6D-8-7]  166.48 65.1 90 top
PQZ03  AON6994_DFN5X6D-8-7  [AON6970_DFN5X6D-8-7]  151.22 68.32 90 bottom
PQZ04  AON6994_DFN5X6D-8-7  [AON6970_DFN5X6D-8-7]  151.21 72.13 270 top
PR1  33_0402_5%  [R_0402]  57.59 122.11 0 top
PR2  0_0402_5%  [R_0402]  90.03 150.33 90 bottom
PR3  100K_0402_1%  [R_0402]  55.61 116.9 180 top
PR4  10K_0402_1%  [R_0402]  59.85 117.71 270 top
PR5  2.2K_0402_5%  [R_0402]  58.57 122.89 0 top
PR6  15K_0402_1%  [R_0402]  54.69 116.07 0 top
PR7  100K_0402_1%  [R_0402]  60.68 114.92 90 top
PR8  1M_0402_5%  [R_0402]  90.88 144.58 270 top
PR9  1M_0402_5%  [R_0402]  102.33 147.62 90 top
PR10  1M_0402_5%  [R_0402]  92.69 148.43 90 bottom
PR11  510K_0402_5%  [R_0402]  96.5 145.66 180 bottom
PR12  1M_0402_5%  [R_0402]  96.5 146.49 180 bottom
PR13  100K_0402_5%  [R_0402]  93.39 152.71 180 top
PR14  10K_0402_1%  [R_0402]  90.03 150.48 0 top
PR15  12K_0402_1%  [R_0402]  91.74 152.71 180 top
PR16  100K_0402_5%  [R_0402]  90.95 151.28 180 top
PR17  56K_0402_5%  [R_0402]  95.65 143.89 0 bottom
PR21  100K_0402_5%  [R_0402]  91.98 148.32 90 top
PR22  100K_0402_5%  [R_0402]  87.79 149.23 270 top
PR31  0_0402_5%  [R_0402]  174.12 32.21 90 top
PR32  3.3K_1206_5%  [R_1206]  171.32 36.87 270 top
PR33  10K_0402_1%  [R_0402]  171.23 27.95 180 top
PR34  1M_0402_1%  [R_0402]  172.92 37.71 0 top
PR35  0_0402_5%  [R_0402]  175.92 33.09 180 top
PR36  1M_0402_1%  [R_0402]  171.9 31.57 0 top
PR37  100_0402_5%  [R_0402]  168.22 40.72 90 top
PR38  1M_0402_1%  [R_0402]  173.79 36.93 0 top
PR39  200_0402_5%  [R_0402]  171.52 42.57 0 top
PR40  100K_0402_1%  [R_0402]  169.15 30.76 90 top
PR41  10K_0402_1%  [R_0402]  170.28 42.07 90 top
PR42  100_0402_5%  [R_0402]  165.44 40.92 90 top
PR43  100K_0402_1%  [R_0402]  177.09 30.08 90 top
PR44  1M_0402_1%  [R_0402]  173.03 29.2 90 top
PR45  1M_0402_1%  [R_0402]  173.34 33.05 180 top
PR46  0_0402_5%  [R_0402]  92.74 148.32 90 top
PR47  300K_0402_5%  [R_0402]  91.82 147.77 90 bottom
PR48  100K_0402_5%  [R_0402]  90.76 149.03 270 bottom
PR49  0_0402_5%  [R_0402]  87.21 143.57 270 bottom
PR50  100K_0402_5%  [R_0402]  91.68 146.34 270 bottom
PR51  0_0402_5%  [R_0402]  92.2 144.69 270 bottom
PR52  16.9K_0402_1%  [R_0402]  46.96 85.29 90 top
PR53  0_0402_5%  [R_0402]  92.42 142.83 225 bottom
PR60  100K_0402_5%  [R_0402]  89.87 149.3 270 bottom
PR61  100K_0402_5%  [R_0402]  46.96 125.73 270 top
PR62  15K_0402_5%  [R_0402]  47.77 124.8 90 top
PR63  100K_0402_5%  [R_0402]  42.05 125.07 270 top
PR64  100K_0402_5%  [R_0402]  43.98 119.77 90 top
PR65  0_0402_5%  [R_0402]  45.97 124.04 0 top
PR66  1M_0402_1%  [R_0402]  46.88 123.22 180 top
PR100  1M_0402_5%  [R_0402]  91.21 152.79 180 bottom
PR301  0_0603_5%  [R0603_0OHM]  21.15 40.01 0 bottom
PR302  499K_0402_1%  [R_0402]  18.16 46.09 90 bottom
PR303  150K_0402_1%  [R_0402]  19.01 46.07 90 bottom
PR304  10K_0402_1%  [R_0402]  19.43 44.52 180 top
PR305  4.7_1206_5%  [R_1206]  26.62 43.85 180 top
PR306  1K_0402_1%  [R_0402]  21.52 47.86 180 bottom
PR307  150K_0402_1%  [R_0402]  20.61 46.99 270 bottom
PR308  150K_0402_1%  [R_0402]  19.83 46.08 90 bottom
PR501  0_0603_5%  [R0603_0OHM]  23.76 100.15 90 bottom
PR502  0_0402_5%  [R0402_0OHM]  26.56 89.6 0 bottom
PR503  0_0402_5%  [R0402_0OHM]  27.34 93.85 270 bottom
PR504  10K_0402_1%  [R_0402]  28.29 91.8 90 bottom
PR505  4.7_1206_5%  [R_1206]  20.4 98.95 90 top
PR506  2.2K_0402_5%  [R_0402]  26.56 90.39 0 bottom
PR507  0_0402_5%  [R0402_0OHM]  27.59 88.4 270 bottom
PR508  1M_0402_5%  [R_0402]  27.49 91.21 180 bottom
PR509  1K_0402_1%  [R_0402]  24.86 92.12 90 bottom
PR510  150K_0402_1%  [R_0402]  24.85 93.85 0 bottom
PR511  150K_0402_1%  [R_0402]  26.58 93.86 270 bottom
PR1801  0_0402_5%  [R0402_0OHM]  173.73 55.04 90 bottom
PR1802  1M_0402_5%  [R_0402]  173.75 56.87 90 bottom
PR1803  100K_0402_5%  [R_0402]  175.04 55.93 0 top
PR1804  4.7_1206_5%  [R_1206]  175.73 53.82 0 top
PR1805  10K_0402_1%  [R_0402]  174.73 58.82 180 bottom
PR1807  20K_0402_1%  [R_0402]  173.82 60.49 0 bottom
PR2501  0_0402_5%  [R0402_0OHM]  77.33 110.04 180 top
PR2502  21.5K_0402_1%  [R_0402]  63.85 112.42 270 top
PR2503  10K_0402_1%  [R_0402]  65.62 109.15 0 top
PR2504  2.2_0402_1%  [R_0402]  71.41 116.34 270 top
PRA01  2.2_0603_5%  [R_0603]  159.46 85.23 0 bottom
PRA02  4.7_1206_5%  [R_1206]  156.04 97.35 90 top
PRA03  3.65K_0603_1%  [R_0603]  160.8 92.29 90 top
PRA04  1_0402_1%  [R_0402]  159.58 93.04 180 top
PRB01  0.02_1206_1%  [R_1206_4P-D]  184.17 60.39 270 bottom
PRB02  2.2_0402_1%  [R_0402]  199.27 48.03 0 bottom
PRB03  2.2_0402_1%  [R_0402]  199.25 47.15 0 bottom
PRB04  0_0603_5%  [R_0603]  199.78 49.13 0 bottom
PRB05  442K_0402_1%  [R_0402]  200.17 50.14 0 bottom
PRB06  3.3_0603_1%  [R_0603]  200.82 46.14 180 bottom
PRB07  100K_0402_5%  [R_0402]  200.45 51.75 180 top
PRB08  1_0805_5%  [R_0805]  202.85 51.82 270 bottom
PRB09  4.7_0402_5%  [R_0402]  202.66 43.65 90 top
PRB10  0_0402_5%  [R0402_0OHM]  204.63 50.64 90 top
PRB11  100K_0402_1%  [R_0402]  207.6 50.48 0 bottom
PRB12  0.01_1206_1%  [R_1206_4P-D]  177.68 40.61 90 bottom
PRB13  0_0402_5%  [R_0402]  204.33 49.66 90 bottom
PRB14  0_0402_5%  [R0402_0OHM]  205.13 50.57 270 bottom
PRB15  4.7_0603_1%  [R_0603]  201.83 40.47 90 bottom
PRB16  0_0402_5%  [R0402_0OHM]  205.97 50.57 270 bottom
PRB17  4.7_1206_5%  [R_1206]  188.91 54.17 270 top
PRB18  4.7_1206_5%  [R_1206]  192.48 44.94 180 top
PRB19  0_0402_5%  [R_0402]  206.78 50.5 270 bottom
PRB20  154K_0402_1%  [R_0402]  162.95 33.63 90 top
PRB21  0_0402_5%  [R0402_0OHM]  204.31 41.27 270 bottom
PRB22  0_0402_5%  [R_0402]  207.6 49.65 0 bottom
PRB23  1M_0402_1%  [R_0402]  163.34 29.52 0 top
PRB24  100K_0402_1%  [R_0402]  206.74 46.27 180 top
PRB25  100K_0402_1%  [R_0402]  208.24 45.4 0 top
PRB26  105K_0402_1%  [R_0402]  208.24 46.21 0 top
PRB27  100K_0402_1%  [R_0402]  208.24 47.86 0 top
PRB28  0_0402_5%  [R0402_0OHM]  208.24 45.19 0 bottom
PRB29  0_0402_5%  [R_0402]  209.15 47.03 180 top
PRB30  499_0402_1%  [R_0402]  208.24 47.04 0 bottom
PRB31  0_0402_5%  [R_0402]  208.05 44.36 0 bottom
PRB32  1_0402_1%  [R_0402]  205.21 40.36 270 bottom
PRB33  10.5K_0402_1%  [R_0402]  208.24 43.54 0 top
PRB34  0_0402_5%  [R0402_0OHM]  209.98 44.34 0 bottom
PRB35  0_0402_5%  [R0402_0OHM]  210 45.19 0 bottom
PRB36  1_0402_1%  [R_0402]  206.16 40.36 270 bottom
PRB37  0_0402_5%  [R_0402]  166.28 35.39 0 top
PRB38  0_0402_5%  [R_0402]  164.59 35.39 0 top
PRB39  100_0402_5%  [R_0402]  208.96 43.54 180 bottom
PRB40  0_0402_5%  [R_0402]  164.6 36.95 90 top
PRB41  0_0402_5%  [R_0402]  163.77 34.56 270 top
PRB42  0_0402_5%  [R_0402]  167.18 32.11 270 top
PRB43  100K_0402_1%  [R_0402]  163.34 28.7 0 top
PRB44  0_0402_5%  [R_0402]  168.82 32.8 0 top
PRF01  47K_0402_5%  [R_0402]  78.71 116.64 270 top
PRF02  2K_0402_1%  [R_0402]  88.15 114.18 90 top
PRF03  10K_0402_1%  [R_0402]  87.2 116.02 90 top
PRF04  2.2_0402_1%  [R_0402]  82.12 111.46 180 top
PRH01  0_0402_5%  [R0402_0OHM]  168.04 47.68 180 bottom
PRH02  1M_0402_1%  [R_0402]  167.17 46.86 0 top
PRH03  0_0402_5%  [R_0402]  168.04 43.48 180 bottom
PRH04  0_0402_5%  [R_0402]  167.1 43.48 0 top
PRH05  100K_0402_5%  [R_0402]  168.09 46.88 180 bottom
PRH06  10_0603_5%  [R_0603]  165.24 42.44 180 bottom
PRH07  4.7_1206_5%  [R_1206]  160.44 47.11 270 top
PRH08  16.9K_0402_1%  [R_0402]  167.19 45.15 0 top
PRH09  31.6K_0402_1%  [R_0402]  167.19 45.13 0 bottom
PRH10  10_0402_1%  [R_0402]  169.78 45.09 180 top
PRH11  2.2_0402_1%  [R_0402]  167.17 44.3 0 bottom
PRH12  1K_0402_1%  [R_0402]  168.08 45.97 180 top
PRH13  0_0402_5%  [R_0402]  168.94 44.25 270 top
PRH14  0_0402_5%  [R_0402]  161.54 41.89 0 top
PRH15  0_0402_5%  [R_0402]  164.09 46.13 0 top
PRH16  750K_0402_1%  [R_0402]  169.59 51.84 180 top
PRH17  1M_0402_1%  [R_0402]  168.68 52.62 0 top
PRH18  100K_0402_5%  [R_0402]  171.47 49.93 180 top
PRH19  0_0402_5%  [R_0402]  166.65 48.89 90 top
PRM01  4.7_1206_5%  [R_1206]  49.04 29.4 0 top
PRM02  2.2_0603_5%  [R_0603]  40.04 30.16 0 top
PRM03  18K_0402_1%  [R_0402]  37.77 25.06 270 top
PRM04  5.1_0603_5%  [R_0603]  34.22 23.91 90 top
PRM05  2.2_0603_5%  [R_0603]  35.49 25.3 270 top
PRM06  10K_0402_1%  [R_0402]  32.72 26.66 0 top
PRM07  453K_0402_1%  [R_0402]  32.73 27.46 0 top
PRM08  0_0402_5%  [R0402_0OHM]  32.73 28.27 0 top
PRM09  0_0402_5%  [R0402_0OHM]  31.81 30.92 0 top
PRM10  60.4K_0402_1%  [R_0402]  34.04 33.13 0 top
PRM11  100K_0402_1%  [R_0402]  33.18 32.2 90 top
PRM12  0_0402_5%  [R_0402]  33.6 29.96 90 top
PRM13  0_0402_5%  [R_0402]  31.36 31.71 0 top
PRS01  1.8M_0402_1%  [R_0402]  49.13 117.09 180 top
PRS02  1K_0402_1%  [R_0402]  46.5 118.74 0 top
PRS03  240K_0402_1%  [R_0402]  52.05 117.22 180 top
PRS04  102K_0402_1%  [R_0402]  46.5 117.79 0 top
PRS05  23.2K_0402_1%  [R_0402]  49.12 117.84 90 top
PRS06  84.5K_0402_1%  [R_0402]  46.58 115.13 270 top
PRS07  100K_0402_5%  [R_0402]  41.18 128.68 270 bottom
PRS08  499K_0402_1%  [R_0402]  51.14 135.86 180 top
PRS09  499K_0402_1%  [R_0402]  66.2 138.54 90 top
PRS10  300K_0402_1%  [R_0402]  65.95 130.56 270 top
PRS11  49.9K_0402_1%  [R_0402]  54.39 135.19 270 top
PRS12  10K_0402_1%  [R_0402]  48.79 126.39 0 top
PRS13  100K_0402_5%  [R_0402]  55.41 132.25 90 top
PRS14  100K_0402_5%  [R_0402]  58.82 130.93 0 top
PRS15  100K_0402_5%  [R_0402]  65.95 128.85 270 top
PRS16  49.9K_0402_1%  [R_0402]  61.45 130.93 180 top
PRS18  0_0402_5%  [R_0402]  61.38 126.37 270 top
PRS23  100K_0402_5%  [R_0402]  52.15 121.89 180 top
PRS25  1M_0402_1%  [R_0402]  57.31 128.38 90 top
PRS26  1M_0402_1%  [R_0402]  65.72 120.83 90 top
PRS27  1M_0402_1%  [R_0402]  65.75 123.43 270 top
PRS28  10K_0402_1%  [R_0402]  62.32 122.56 90 top
PRS29  100K_0402_1%  [R_0402]  64.94 124.26 0 top
PRS30  100K_0402_1%  [R_0402]  64.18 117.03 180 top
PRS32  0_0402_5%  [R_0402]  45.7 117.79 180 top
PRS33  0_0402_5%  [R_0402]  52.15 122.72 180 top
PRS34  10K_0402_1%  [R_0402]  62.26 124.44 90 top
PRS35  0_0402_5%  [R_0402]  66.39 127.14 270 top
PRS36  300K_0402_1%  [R_0402]  53.97 133.46 270 top
PRS37  100K_0402_5%  [R_0402]  52.82 131 180 top
PRS38  0_0402_5%  [R_0402]  49.36 127.54 90 top
PRS39  0_0402_5%  [R_0402]  47.41 116 90 top
PRS40  0_0402_5%  [R_0402]  52.21 120.9 180 top
PRS41  0_0402_5%  [R_0402]  52.95 122.21 270 top
PRS42  0_0402_5%  [R_0402]  60.38 124.63 180 top
PRS43  0_0402_5%  [R_0402]  52.68 123.66 0 top
PRS44  0_0402_5%  [R_0402]  54.38 123.66 0 top
PRS45  0_0402_5%  [R_0402]  70.67 133.87 90 top
PRS61  49.9K_0402_1%  [R_0402]  55.46 136 270 top
PRS62  499K_0402_1%  [R_0402]  47.24 134.93 90 top
PRS63  300K_0402_1%  [R_0402]  44.13 133.8 180 top
PRS64  0_0402_5%  [R_0402]  39.85 127.83 270 top
PRS65  10K_0402_1%  [R_0402]  41.6 126.92 180 top
PRS66  100K_0402_5%  [R_0402]  42.65 133.01 225 top
PRV01  0_0603_5%  [R0603_0OHM]  77.12 133.79 0 top
PRV02  32.4K_0402_1%  [R_0402]  73.76 133.71 90 top
PRV03  10K_0402_1%  [R_0402]  67.22 120.79 0 top
PRV04  10K_0402_1%  [R_0402]  74.65 133.71 90 top
PRV05  10K_0402_1%  [R_0402]  75.47 133.71 90 top
PRV06  4.7_1206_5%  [R_1206]  90.92 134.44 270 top
PRV07  3.65K_0603_1%  [R_0603]  66.96 121.79 0 top
PRV08  1_0402_1%  [R_0402]  66.89 123.71 270 top
PRV09  100K_0402_1%  [R_0402]  69.95 132.33 180 top
PRV10  100K_0402_1%  [R_0402]  71.79 133.71 90 top
PRV12  0_0402_5%  [R_0402]  67.92 131.14 0 top
PRV13  1_0603_5%  [R_0603]  79.6 131.06 270 top
PRV14  0_0402_5%  [R_0402]  67.92 130.31 0 top
PRV15  10K_0402_5%  [R_0402]  68.73 129.34 0 top
PRV16  133K_0402_1%  [R_0402]  67.98 128.53 270 top
PRV17  100K_0402_1%  [R_0402]  79.49 125.85 180 top
PRV18  150K_0402_1%  [R_0402]  67.15 125.71 90 top
PRV19  13.3K_0402_1%  [R_0402]  67.98 126.63 270 top
PRV20  0_0402_5%  [R0402_0OHM]  78.59 125.05 0 top
PRV21  0_0603_5%  [R0603_0OHM]  78.39 127.25 0 top
PRV22  10K_0402_1%  [R_0402]  70.25 120.25 270 top
PRV23  4.7_1206_5%  [R_1206]  90.97 125.45 90 top
PRV24  3.65K_0603_1%  [R_0603]  68.08 118.46 90 top
PRV25  1_0402_1%  [R_0402]  71.92 121.84 90 top
PRV26  301_0402_1%  [R_0402]  73.76 124.53 270 top
PRV27  121K_0402_1%  [R_0402]  77.05 122.61 0 top
PRV28  2.61K_0402_1%  [R_0402]  70.9 122.03 270 top
PRV29  1.37K_0402_1%  [R_0402]  74.58 124.53 270 top
PRV30  11K_0402_1%  [R_0402]  70.07 123.49 90 top
PRV31  22.1K_0402_1%  [R_0402]  74.52 121.99 270 top
PRV32  2K_0402_1%  [R_0402]  73.69 121.99 270 top
PRV33  665_0402_1%  [R_0402]  72.68 123.62 90 top
PRV34  0_0402_5%  [R0402_0OHM]  76.31 123.57 180 top
PRV35  100_0402_1%  [R_0402]  71.85 123.62 90 top
PRV36  0_0402_5%  [R0402_0OHM]  77.57 124.44 90 top
PRW01  0_0402_5%  [R_0402]  139.86 112.35 270 bottom
PRW02  1M_0402_1%  [R_0402]  139.07 111.44 90 bottom
PRW03  0_0402_5%  [R_0402]  147.44 111.47 180 top
PRW04  0_0402_5%  [R_0402]  145.14 111.45 90 bottom
PRW05  100K_0402_5%  [R_0402]  140.76 112.36 270 bottom
PRW06  10_0603_5%  [R_0603]  144.81 108.13 0 top
PRW07  4.7_1206_5%  [R_1206]  147.78 109.77 0 top
PRW09  39.2K_0402_1%  [R_0402]  143.46 111.49 90 bottom
PRW10  31.6K_0402_1%  [R_0402]  142.55 112.37 180 bottom
PRW11  2.2_0402_1%  [R_0402]  144.46 110.36 225 top
PRW12  1K_0402_1%  [R_0402]  146.09 114.36 225 bottom
PRZ01  2K_0402_1%  [R_0402]  162.04 88.69 180 bottom
PRZ02  10_0402_5%  [R_0402]  122.58 81.76 90 top
PRZ03  732_0402_1%  [R_0402]  161.96 90.38 270 bottom
PRZ04  36.5K_0402_1%  [R_0402]  159.24 88.84 0 bottom
PRZ05  34K_0402_1%  [R_0402]  157.92 87.97 180 bottom
PRZ06  0_0402_5%  [R0402_0OHM]  162.86 92.18 270 bottom
PRZ07  301_0402_1%  [R_0402]  161.17 90.38 270 bottom
PRZ08  2.61K_0402_1%  [R_0402]  158.63 91.15 90 bottom
PRZ09  11K_0402_1%  [R_0402]  161.43 91.39 270 top
PRZ10  191_0402_1%  [R_0402]  158.92 90.91 270 top
PRZ11  100_0402_1%  [R_0402]  159.71 90.91 270 top
PRZ12  150K_0402_1%  [R_0402]  157.44 89.73 90 bottom
PRZ13  13.3K_0402_1%  [R_0402]  157.01 93.25 270 top
PRZ14  133K_0402_1%  [R_0402]  156.6 89.75 90 bottom
PRZ15  100K_0402_1%  [R_0402]  155.48 93.25 270 top
PRZ16  0_0402_5%  [R0402_0OHM]  154.72 93.25 270 top
PRZ17  1_0603_5%  [R_0603]  153.83 82.09 0 top
PRZ19  0_0402_5%  [R0402_0OHM]  152.03 92.39 0 top
PRZ20  133K_0402_1%  [R_0402]  152.07 90.01 90 bottom
PRZ21  2.2_0603_5%  [R_0603]  157.31 82.72 270 top
PRZ22  10K_0402_1%  [R_0402]  148.17 79.9 90 top
PRZ23  4.7_1206_5%  [R_1206]  164.99 61.1 180 top
PRZ24  100K_0402_5%  [R_0402]  150.8 82.69 90 bottom
PRZ25  150K_0402_1%  [R_0402]  150.72 91.18 180 top
PRZ26  13.3K_0402_1%  [R_0402]  149.39 90.41 0 top
PRZ27  3.65K_0603_1%  [R_0603]  149.2 81.3 270 top
PRZ28  1_0402_1%  [R_0402]  150.24 79.95 90 top
PRZ29  301_0402_1%  [R_0402]  146.95 86.62 0 top
PRZ30  210K_0402_1%  [R_0402]  150.99 84.84 0 bottom
PRZ31  698_0402_1%  [R_0402]  147.86 84.89 90 top
PRZ32  2.61K_0402_1%  [R_0402]  147.81 87.27 180 bottom
PRZ33  11K_0402_1%  [R_0402]  147.81 88.06 180 bottom
PRZ34  36.5K_0402_1%  [R_0402]  148.67 85.81 270 top
PRZ35  2K_0402_1%  [R_0402]  149.49 85.81 270 top
PRZ36  340_0402_1%  [R_0402]  147.73 88.86 90 bottom
PRZ37  10_0402_5%  [R_0402]  146.97 82.37 270 top
PRZ38  0_0402_5%  [R0402_0OHM]  147 84.06 270 top
PRZ39  100_0402_1%  [R_0402]  146.84 88.84 90 bottom
PRZ40  0_0402_5%  [R0402_0OHM]  150.28 88.18 90 bottom
PRZ41  2.2_0603_5%  [R_0603]  151.62 82.9 270 top
PRZ42  10K_0402_1%  [R_0402]  150.25 79.95 90 bottom
PRZ43  10_0402_5%  [R_0402]  151.47 89.09 0 bottom
PRZ44  4.7_1206_5%  [R_1206]  155.47 61.15 0 top
PRZ45  3.65K_0603_1%  [R_0603]  149.19 81.3 270 bottom
PRZ46  1_0402_1%  [R_0402]  148.18 79.92 90 bottom
PRZ47  0_0402_5%  [R_0402]  152.03 93.18 0 top
PU1  -  [RT9069-33GB_SOT23-5]  82.11 144.37 270 top
PU2  -  [SN74AHC1G08DCKR_SC70-5]  95.91 147.73 90 top
PU301  -  [SY8286BRAC_QFN20_3X3]  20.79 41.49 90 bottom
PU501  SY8180CRAC_QFN20_3X3  [SY8288CRAC_QFN20_3X3]  24.66 98.72 270 bottom
PU1801  -  [RT8061AZQW_WDFN10_3X3]  177.85 56.52 180 bottom
PU2501  -  [RT9059GSP_SO8]  71.51 110.42 90 top
PUB01  -  [ISL9538HRTZ-T_TQFN32_4X4]  205.97 43.79 90 bottom
PUB02  -  [SN74AHC1G08DCKR_SC70-5]  164.85 34.32 270 top
PUF01  -  [RT9059GSP_SO8]  80.36 116.51 270 top
PUH01  -  [RT6226AGQUF_UQFN12_3X3]  164.85 44.03 90 bottom
PUM01  -  [RT8207PGQW_WQFN20_3X3]  37.65 30.36 180 top
PUS01  AS393MMTR-G1_MSOP8  [LM393DGKR_VSSOP8]  48.98 115.91 0 top
PUS02  -  [SN74AHC1G08DCKR_SC70-5]  59.69 125.79 90 top
PUS03  -  [TC7SH32FU_SSOP5]  52.44 126.04 270 top
PUS04  RT9058-33GX SOT-89 3P  [AP2204R-5P0TRG1_SOT89-3]  77.4 144.14 0 top
PUV01  ISL62771HRTZ-T_TQFN40_5X5  [ISL62771HRTZ-T_TQFN40_5X5-S]  71.69 131.44 270 top
PUW01  -  [RT6226AGQUF_UQFN12_3X3]  144.7 109.12 180 bottom
PUZ01  ISL62771HRTZ-T_TQFN40_5X5  [ISL62771HRTZ-T_TQFN40_5X5-S]  156.37 89.82 180 top
Q1  -  [LN2306LT1G_SOT23-3]  117.13 28.99 0 top
Q2  NTK3139PT1G_SOT723-3  [2N7002K_SOT23-3]  113.19 31.14 180 top
Q3  -  [LN2306LT1G_SOT23-3]  46.77 60.23 0 top
Q4  -  [2N7002K_SOT23-3]  108.75 30.18 180 top
Q5  -  [LN2306LT1G_SOT23-3]  79.18 37.84 90 top
Q6  DDTA144VCA-7-F-GP  [2N7002K_SOT23-3]  74.48 37.78 90 top
